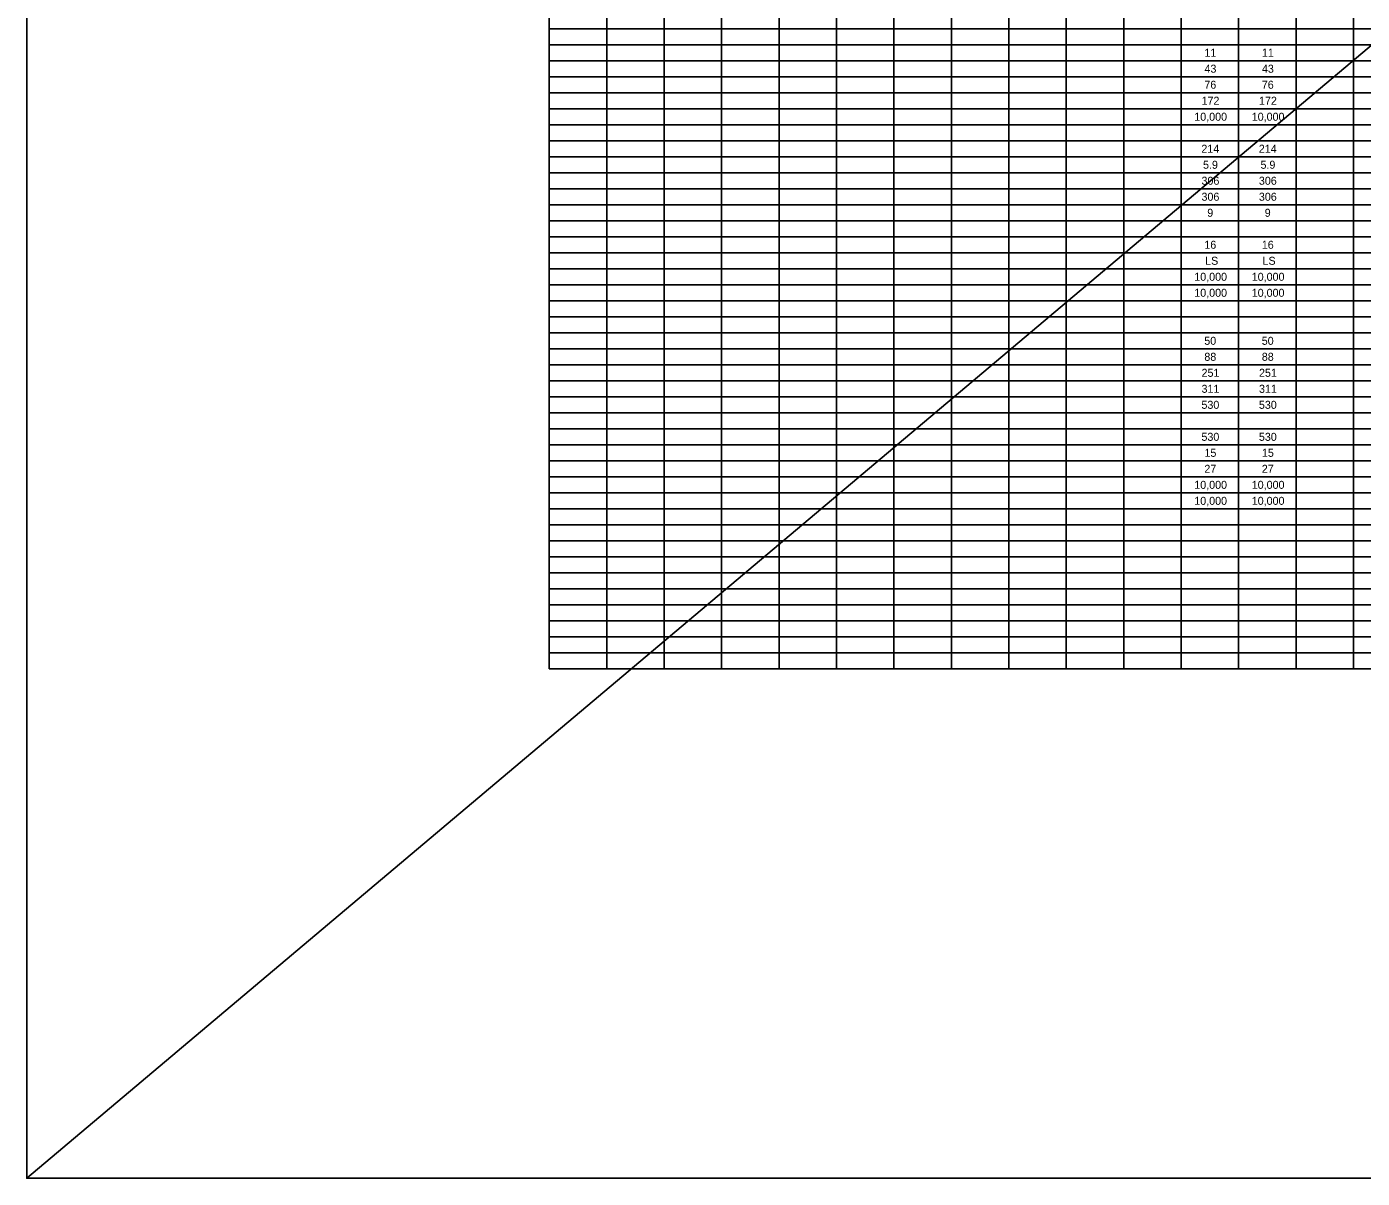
# Model space of a CAD drawing. Extents: x -58.2 to 35.9, y -5.7 to 34.4.
# Drawn here: x -58.21 to -34.85, y -5.73 to 14.42 of the extents above; entities that cross this region are included whole.
import ezdxf

# ---------------------------------------------------------------- set-up
doc = ezdxf.new("R2010")
doc.units = 0
for name, color, linetype in [('SC_Scratch1', 7, 'Continuous'), ('SH_Data', 7, 'Continuous'), ('SH_Text', 7, 'Continuous')]:
    doc.layers.add(name, color=color, linetype=linetype)

msp = doc.modelspace()

# ---------------------------------------------------------------- linework, layer by layer
at = {"layer": 'SC_Scratch1'}
msp.add_line((-58.206, -5.726), (-10.544, 34.449), dxfattribs=at)
msp.add_lwpolyline([(-58.206, 34.449), (-10.544, 34.449), (-10.544, -5.726), (-58.206, -5.726)], close=True, dxfattribs=at)
at = {"layer": 'SH_Data'}
for p, q in [((-49.066, 24.187), (-49.066, 3.187)), ((-37.01, 24.187), (-37.01, 3.187)), ((-35, 24.187), (-35, 3.187)), ((-48.061, 23.627), (-48.061, 3.187)), ((-47.057, 23.627), (-47.057, 3.187)), ((-46.052, 23.627), (-46.052, 3.187)), ((-45.047, 23.627), (-45.047, 3.187)), ((-44.043, 23.627), (-44.043, 3.187)), ((-43.038, 23.627), (-43.038, 3.187)), ((-42.033, 23.627), (-42.033, 3.187)), ((-41.028, 23.627), (-41.028, 3.187)), ((-40.024, 23.627), (-40.024, 3.187)), ((-39.019, 23.627), (-39.019, 3.187)), ((-38.014, 23.627), (-38.014, 3.187)), ((-36.005, 23.627), (-36.005, 3.187)), ((-49.066, 14.387), (-18.563, 14.387)), ((-49.066, 14.107), (-18.563, 14.107)), ((-49.066, 13.827), (-18.563, 13.827)), ((-49.066, 13.547), (-18.563, 13.547)), ((-49.066, 13.267), (-18.563, 13.267)), ((-49.066, 12.987), (-18.563, 12.987)), ((-49.066, 12.707), (-18.563, 12.707)), ((-49.066, 12.427), (-18.563, 12.427)), ((-49.066, 12.147), (-18.563, 12.147)), ((-49.066, 11.867), (-18.563, 11.867)), ((-49.066, 11.587), (-18.563, 11.587)), ((-49.066, 11.307), (-18.563, 11.307)), ((-49.066, 11.027), (-18.563, 11.027)), ((-49.066, 10.747), (-18.563, 10.747)), ((-49.066, 10.467), (-18.563, 10.467)), ((-49.066, 10.187), (-18.563, 10.187)), ((-49.066, 9.907), (-18.563, 9.907)), ((-49.066, 9.627), (-18.563, 9.627)), ((-49.066, 9.347), (-18.563, 9.347)), ((-49.066, 9.067), (-18.563, 9.067)), ((-49.066, 8.787), (-18.563, 8.787)), ((-49.066, 8.507), (-18.563, 8.507)), ((-49.066, 8.227), (-18.563, 8.227)), ((-49.066, 7.947), (-18.563, 7.947)), ((-49.066, 7.667), (-18.563, 7.667)), ((-49.066, 7.387), (-18.563, 7.387)), ((-49.066, 7.107), (-18.563, 7.107)), ((-49.066, 6.827), (-18.563, 6.827)), ((-49.066, 6.547), (-18.563, 6.547)), ((-49.066, 6.267), (-18.563, 6.267)), ((-49.066, 5.987), (-18.563, 5.987)), ((-49.066, 5.707), (-18.563, 5.707)), ((-49.066, 5.427), (-18.563, 5.427)), ((-49.066, 5.147), (-18.563, 5.147)), ((-49.066, 4.867), (-18.563, 4.867)), ((-49.066, 4.587), (-18.563, 4.587)), ((-49.066, 4.307), (-18.563, 4.307)), ((-49.066, 4.027), (-18.563, 4.027)), ((-49.066, 3.747), (-18.563, 3.747)), ((-49.066, 3.467), (-18.563, 3.467)), ((-49.066, 3.187), (-18.563, 3.187))]:
    msp.add_line(p, q, dxfattribs=at)

# ---------------------------------------------------------------- texts
at = {"layer": 'SH_Text'}
for s, p in [('11', (-37.607, 13.897)), ('11', (-36.602, 13.897)), ('43', (-37.606, 13.617)), ('43', (-36.601, 13.617)), ('76', (-37.608, 13.337)), ('76', (-36.603, 13.337)), ('172', (-37.657, 13.057)), ('172', (-36.652, 13.057)), ('10,000', (-37.784, 12.777)), ('10,000', (-36.779, 12.777)), ('214', (-37.66, 12.217)), ('214', (-36.655, 12.217)), ('5.9', (-37.631, 11.937)), ('5.9', (-36.626, 11.937)), ('306', (-37.658, 11.657)), ('306', (-36.654, 11.657)), ('306', (-37.658, 11.377)), ('306', (-36.654, 11.377)), ('9', (-37.557, 11.097)), ('9', (-36.552, 11.097)), ('16', (-37.608, 10.537)), ('16', (-36.603, 10.537)), ('LS', (-37.594, 10.257)), ('LS', (-36.59, 10.257)), ('10,000', (-37.784, 9.977)), ('10,000', (-36.779, 9.977)), ('10,000', (-37.784, 9.697)), ('10,000', (-36.779, 9.697)), ('50', (-37.609, 8.857)), ('50', (-36.604, 8.857)), ('88', (-37.608, 8.577)), ('88', (-36.603, 8.577)), ('251', (-37.657, 8.297)), ('251', (-36.652, 8.297)), ('311', (-37.657, 8.017)), ('311', (-36.652, 8.017)), ('530', (-37.659, 7.737)), ('530', (-36.654, 7.737)), ('530', (-37.659, 7.177)), ('530', (-36.654, 7.177)), ('15', (-37.606, 6.897)), ('15', (-36.601, 6.897)), ('27', (-37.608, 6.617)), ('27', (-36.603, 6.617)), ('10,000', (-37.784, 6.337)), ('10,000', (-36.779, 6.337)), ('10,000', (-37.784, 6.057)), ('10,000', (-36.779, 6.057))]:
    msp.add_text(s, height=0.14, dxfattribs=at).set_placement(p)

doc.saveas('drawing.dxf')
